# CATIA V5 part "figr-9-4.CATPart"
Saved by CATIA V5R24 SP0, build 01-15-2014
Part number: Part1
Bounding box of the stored display mesh (mm): x -71.324 to 69.61, y -139.735 to 0, z 0 to 45
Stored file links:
  D:\KAVITA\CATIA V5-6R2014 Project_ Kavita\CATIA V5-6R2014_partfiles\Partfiles\c09_catia_v5-6r2014_prt\figr-9-4.CATPart
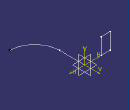
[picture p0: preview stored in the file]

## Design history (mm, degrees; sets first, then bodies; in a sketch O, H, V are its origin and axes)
Body1 (main body)
  Sketch1 on xy-plane, origin (0, 0, 0), H (1, 0, 0), V (0, 1, 0)
    line L1 (0, 0) -> (0, -70.1255)
    arc A1 centre (69.6095, -70.1255) radius 69.6095 from (0, -70.1255) to (69.6095, -139.7351) ccw
    vertical: L1 V
    tangency: A1 L1
  Sketch2 on zx-plane, origin (0, 0, 0), H (-1, 0, 0), V (0, 0, 1)
    point P1 (46.3244, 0)
    line L1 (46.3244, 0) -> (71.3244, 0)
    line L2 (71.3244, 0) -> (71.3244, 45)
    line L3 (71.3244, 45) -> (46.3244, 45)
    line L4 (46.3244, 45) -> (46.3244, 0)
    length L3 = 25
    length L2 = 45
    coincidence: P1 H
    horizontal: L1 H, L3 H
    vertical: L2 V, L4 V
  Rib1: profile Sketch2, centre curve Sketch1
